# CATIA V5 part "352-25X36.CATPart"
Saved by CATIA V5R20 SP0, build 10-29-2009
Part number: 352-25X36
Definition: NONE
Nomenclature: 352-25X36
Source: Unknown
Description: 352-25X36
Bounding box of the stored display mesh (mm): x 0 to 36, y -17 to 17, z -17 to 17
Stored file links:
  C:\Users\Utente\Desktop\IO LAVORO\3D X SITO CF\X SITO\PLASTICA\352\352-25X36.CATPart
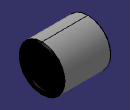
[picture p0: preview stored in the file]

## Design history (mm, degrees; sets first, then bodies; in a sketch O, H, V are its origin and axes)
Body1 "352-25X36" (main body)
  Solid1: solid without history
